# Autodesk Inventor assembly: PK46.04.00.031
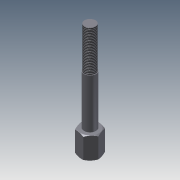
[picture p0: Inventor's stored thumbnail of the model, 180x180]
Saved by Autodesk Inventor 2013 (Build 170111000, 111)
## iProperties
Created: 2005-04
Part Number: PK46.04.00.031
Document SubType Name: Assembly
Designer: salex
Manufacturer: Standard
Standards Organization: Custom
Author: salex
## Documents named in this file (3)
- D:\FrontLoaderVault\Data\Assy, Chassis, Front\PK46.04.00.031.iam
- D:\FrontLoaderVault\Data\Assy, Chassis, Front\027.15.23.127.ipt
- D:\FrontLoaderVault\Data\Assy, Chassis, Front\027.13.15.227.ipt
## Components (2 placed, 2 different names)
1. 027.15.23.127:1 — Insert:1
2. 027.13.15.227:1 — Insert:1
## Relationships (1: Insert 1)
- Insert:1: 027.15.23.127:1 ↔ 027.13.15.227:1
